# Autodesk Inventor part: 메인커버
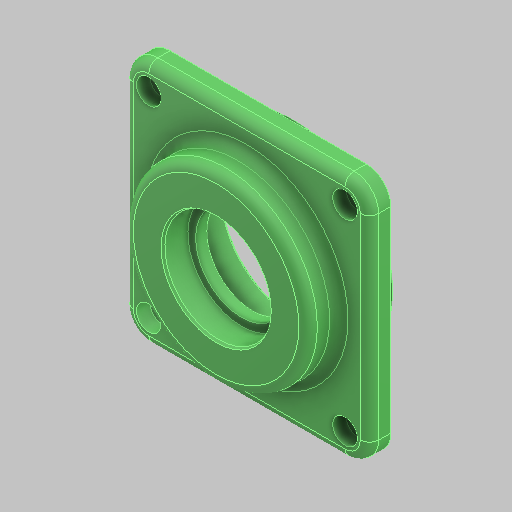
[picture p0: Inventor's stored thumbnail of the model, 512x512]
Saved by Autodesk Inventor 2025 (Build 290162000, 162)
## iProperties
Created: 2024-08
Part Number: 메인커버
Material: 알루미늄 6061
Document SubType Name: Modeling
Designer: 현기
Density: 2.71 g/cm^3
Appearance: 기본값
Author: jhkim
Sending System: Autodesk Inventor 2025
Preprocessor: ST-DEVELOPER v20
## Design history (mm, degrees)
feature "솔리드1"
node "솔리드2"
